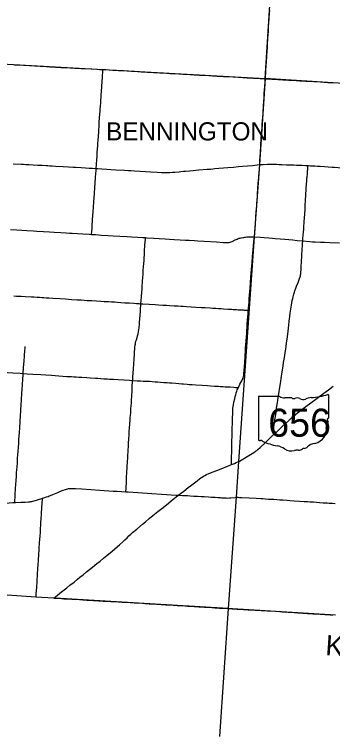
# Model space of a CAD drawing. Extents: x 1815539 to 1947826, y 273303 to 993194.
# Drawn here: x 1889640 to 1905397, y 849557 to 885394 of the extents above; entities that cross this region are included whole.
import ezdxf

# ---------------------------------------------------------------- set-up
doc = ezdxf.new("R2010")
doc.units = 0
for name, color, linetype in [('GM_X_Adjacent_County_Text', 7, 'Continuous'), ('GM_X_County', 7, 'Continuous'), ('GM_X_County_Road', 7, 'Continuous'), ('GM_X_State_Route', 7, 'Continuous'), ('GM_X_Township', 7, 'Continuous'), ('GM_X_Township_Road', 7, 'Continuous'), ('GM_X_Township_Text', 7, 'Continuous'), ('PV_X_EOP', 7, 'Continuous'), ('SC_Shading3', 7, 'Continuous')]:
    doc.layers.add(name, color=color, linetype=linetype)

msp = doc.modelspace()

# ---------------------------------------------------------------- linework, layer by layer
at = {"layer": 'GM_X_County'}
msp.add_lwpolyline([(1905546, 855583), (1900992, 855867), (1900447, 855895), (1900228, 855908), (1896895, 856116), (1891937, 856405), (1891588, 856432), (1890695, 856480), (1886895, 856734)], dxfattribs=at)
at = {"layer": 'GM_X_County_Road'}
for points in [[(1902064, 882205), (1902069, 882271), (1902089, 882549), (1902097, 882680), (1902104, 882794), (1902124, 883088), (1902135, 883252), (1902142, 883350), (1902160, 883579), (1902171, 883759), (1902179, 883906), (1902198, 884217), (1902218, 884561), (1902232, 884790), (1902259, 885182), (1902277, 885477), (1902284, 885593)], [(1901788, 877939), (1901801, 878159), (1901811, 878322), (1901825, 878552), (1901847, 878896), (1901869, 879256), (1901894, 879616), (1901903, 879780), (1901914, 879927), (1901928, 880124), (1901938, 880255), (1901953, 880500), (1901979, 880877), (1901991, 881073), (1902003, 881270), (1902016, 881499), (1902024, 881630), (1902038, 881827), (1902052, 882023), (1902064, 882205)], [(1902064, 882205), (1902240, 882194), (1902387, 882186), (1902682, 882168), (1902927, 882155), (1903239, 882138), (1903403, 882129), (1903779, 882107), (1903910, 882101), (1904074, 882090), (1904222, 882082), (1904467, 882068), (1904598, 882059), (1904795, 882046), (1904975, 882034), (1905171, 882022), (1905449, 882003)], [(1901526, 874352), (1901541, 874540), (1901560, 874771), (1901575, 874967), (1901585, 875124), (1901590, 875197), (1901597, 875311), (1901620, 875605), (1901640, 875884), (1901650, 876015), (1901672, 876326), (1901686, 876522), (1901701, 876718), (1901721, 876997), (1901743, 877291), (1901752, 877406), (1901760, 877537), (1901773, 877733), (1901788, 877939)], [(1891033, 861391), (1891103, 861412), (1891228, 861451), (1891306, 861477), (1891367, 861499), (1891427, 861524), (1891533, 861569), (1891790, 861677), (1891927, 861733), (1892050, 861779), (1892174, 861823), (1892221, 861838), (1892284, 861856), (1892317, 861863), (1892340, 861867), (1892376, 861873), (1892414, 861874), (1892457, 861874), (1892511, 861873), (1892657, 861863), (1892975, 861844), (1893875, 861784), (1894530, 861742), (1894727, 861729), (1895156, 861701)], [(1895156, 861701), (1895267, 861694), (1895758, 861664), (1896445, 861620), (1896920, 861591), (1897657, 861542), (1897691, 861539), (1897763, 861534)], [(1897763, 861534), (1897839, 861530), (1897960, 861524), (1898208, 861515), (1898338, 861507), (1898526, 861493), (1898704, 861483), (1898895, 861472), (1899045, 861464), (1899246, 861452), (1899400, 861441), (1899581, 861430), (1899712, 861422), (1899842, 861413), (1899917, 861408)], [(1887166, 860572), (1887216, 860614), (1887308, 860683), (1887494, 860818), (1887640, 860924), (1887720, 860982), (1887748, 861000), (1887777, 861016), (1887808, 861028), (1887824, 861033), (1887840, 861037), (1887873, 861041), (1888069, 861059), (1888315, 861078), (1888511, 861093), (1888609, 861101), (1889018, 861133), (1889182, 861145), (1889378, 861158), (1889558, 861167), (1889657, 861171)], [(1889657, 861171), (1889692, 861173), (1889953, 861185), (1890166, 861196), (1890328, 861205), (1890402, 861211), (1890451, 861216), (1890507, 861229), (1890555, 861240), (1890618, 861258), (1890993, 861378), (1891033, 861391)], [(1899917, 861408), (1899957, 861406), (1900023, 861403), (1900085, 861399)], [(1900085, 861399), (1900121, 861397), (1900203, 861395), (1900285, 861397), (1900367, 861402), (1900580, 861425), (1900581, 861425)], [(1900581, 861425), (1900655, 861430), (1900723, 861431), (1900792, 861429), (1900906, 861425), (1901275, 861404), (1901620, 861382), (1901838, 861371), (1901949, 861365), (1902082, 861356), (1902229, 861346), (1902336, 861340), (1902491, 861330), (1902642, 861318), (1902782, 861311), (1902943, 861304), (1903156, 861289), (1903274, 861276), (1903498, 861259), (1903761, 861241), (1903998, 861229), (1904157, 861221), (1904294, 861213), (1904450, 861200), (1904752, 861174), (1904940, 861161), (1905132, 861150), (1905237, 861146), (1905393, 861139), (1905528, 861131)], [(1891583, 856425), (1891639, 856423), (1891746, 856417), (1891965, 856405)], [(1891965, 856405), (1892090, 856398), (1892301, 856385), (1892481, 856374), (1892856, 856351), (1893019, 856342), (1893232, 856329), (1893543, 856312), (1893805, 856297), (1893879, 856293), (1894034, 856284), (1894263, 856272), (1894410, 856264), (1894495, 856259)], [(1894495, 856259), (1894590, 856253), (1894770, 856241), (1894983, 856228), (1895376, 856205), (1895572, 856194), (1895703, 856186), (1895981, 856169), (1896095, 856161), (1896177, 856156), (1896242, 856153), (1896308, 856149), (1896553, 856136), (1896684, 856128), (1896799, 856122), (1896913, 856115), (1896923, 856115)], [(1896923, 856115), (1897028, 856108), (1897142, 856101), (1897208, 856097), (1897503, 856079), (1897601, 856072), (1897699, 856066), (1897780, 856061), (1897911, 856054), (1898222, 856035), (1898370, 856027), (1898550, 856015), (1898713, 856004), (1898778, 856000), (1898893, 855993), (1899057, 855983), (1899416, 855960), (1899563, 855950), (1899678, 855942), (1899792, 855935), (1899988, 855922), (1900186, 855910)], [(1900186, 855910), (1900418, 855898), (1900516, 855892), (1900679, 855880), (1900711, 855878), (1900792, 855875), (1900873, 855872), (1900987, 855865), (1901117, 855858), (1901216, 855852), (1901412, 855841), (1901477, 855838), (1901559, 855834), (1901730, 855823), (1901855, 855815), (1902001, 855805), (1902166, 855796), (1902566, 855776), (1902784, 855762), (1902899, 855755), (1903029, 855748), (1903195, 855737), (1903359, 855726), (1903490, 855716), (1903572, 855710), (1903686, 855702), (1903866, 855689), (1903948, 855683), (1904151, 855671), (1904291, 855661), (1904422, 855654), (1904635, 855643), (1904787, 855633), (1904900, 855626), (1905019, 855619), (1905109, 855614), (1905174, 855610), (1905275, 855603), (1905405, 855595)]]:
    msp.add_lwpolyline(points, dxfattribs=at)
at = {"layer": 'GM_X_State_Route'}
for points in [[(1889446, 874722), (1889758, 874704), (1890249, 874670), (1890576, 874650), (1890756, 874639), (1891084, 874620), (1891379, 874602), (1891608, 874588), (1891936, 874570), (1892198, 874556), (1892362, 874545), (1892493, 874537), (1892771, 874520), (1893033, 874504), (1893344, 874485), (1893457, 874478), (1893655, 874466), (1893950, 874446), (1894278, 874425), (1894523, 874409), (1894867, 874390), (1895227, 874371), (1895440, 874359), (1895735, 874340), (1895999, 874324), (1896130, 874316), (1896194, 874311), (1896545, 874289), (1896816, 874273), (1897111, 874256), (1897318, 874243), (1897553, 874228), (1897848, 874210), (1898110, 874195), (1898295, 874184), (1898552, 874168), (1898716, 874157), (1899043, 874137), (1899649, 874101), (1899993, 874075), (1900091, 874069), (1900157, 874068), (1900207, 874070), (1900240, 874073), (1900272, 874079), (1900320, 874091), (1900367, 874108), (1900428, 874133), (1900576, 874203), (1900666, 874244), (1900727, 874268), (1900773, 874283), (1900820, 874296), (1900868, 874306), (1900948, 874320), (1901007, 874330), (1901046, 874336), (1901092, 874342), (1901155, 874349), (1901230, 874356), (1901307, 874358), (1901372, 874358), (1901479, 874355), (1901526, 874352), (1901827, 874333), (1902007, 874320), (1902236, 874305), (1902416, 874291), (1902563, 874278), (1902808, 874257), (1903037, 874237), (1903429, 874202), (1903641, 874181), (1903918, 874156), (1903926, 874155), (1904277, 874122), (1904408, 874113), (1904539, 874106), (1904801, 874094), (1904997, 874087), (1905259, 874074), (1905735, 874054)], [(1891583, 856425), (1891666, 856492), (1891977, 856734), (1892233, 856938), (1892386, 857062), (1892590, 857227), (1892769, 857371), (1892883, 857465), (1893036, 857588), (1893214, 857733), (1893354, 857847), (1893507, 857970), (1893725, 858144), (1893878, 858268), (1894056, 858412), (1894208, 858537), (1894474, 858756), (1894751, 858988), (1894850, 859074), (1895018, 859229), (1895114, 859320), (1895219, 859423), (1895313, 859515), (1895397, 859593), (1895495, 859680), (1895694, 859850), (1895983, 860092), (1896133, 860220), (1896321, 860378), (1896502, 860529), (1896742, 860718), (1896934, 860871), (1897088, 860994), (1897266, 861138), (1897408, 861250), (1897574, 861383), (1897740, 861517), (1897763, 861534), (1897869, 861618), (1898025, 861739), (1898243, 861912), (1898360, 862002), (1898683, 862253), (1898814, 862353), (1898880, 862401), (1898934, 862437), (1899004, 862479), (1899076, 862519), (1899149, 862555), (1899239, 862595), (1899436, 862676), (1899665, 862767), (1899878, 862851), (1900198, 862977), (1900351, 863038), (1900389, 863053), (1900536, 863112), (1900631, 863153), (1900707, 863188), (1900715, 863192), (1900793, 863231), (1900864, 863272), (1900956, 863324), (1901044, 863377), (1901174, 863454), (1901326, 863549), (1901497, 863655), (1901582, 863713), (1901644, 863757), (1901696, 863800), (1901806, 863898), (1902080, 864158), (1902377, 864442), (1902555, 864611), (1902581, 864636), (1902759, 864802), (1902926, 864957), (1903205, 865215), (1903322, 865323), (1903470, 865459), (1903569, 865546), (1903638, 865602), (1903736, 865683), (1903878, 865788), (1904009, 865886), (1904326, 866120), (1904577, 866305), (1904761, 866443), (1904971, 866600), (1905195, 866767), (1905433, 866942)]]:
    msp.add_lwpolyline(points, dxfattribs=at)
at = {"layer": 'GM_X_Township'}
for points in [[(1929313, 880637), (1926519, 880798), (1923978, 880945), (1923826, 880954), (1918127, 881283), (1915079, 881414), (1912418, 881561), (1907482, 881867), (1902065, 882212), (1902276, 885593), (1902366, 887154), (1902378, 887248), (1902624, 890798), (1902935, 895772), (1903241, 901246), (1903453, 905734), (1903500, 906547), (1903661, 909327)], [(1888679, 882953), (1894036, 882664), (1902065, 882212), (1901776, 877944), (1901523, 874357), (1900741, 863210), (1900616, 861438), (1900228, 855908)]]:
    msp.add_lwpolyline(points, dxfattribs=at)
at = {"layer": 'GM_X_Township_Road'}
for points in [[(1889638, 882899), (1889900, 882886), (1890081, 882876), (1890195, 882871), (1890384, 882860), (1890638, 882845), (1890769, 882838), (1890917, 882829), (1891064, 882822), (1891228, 882813), (1891394, 882800), (1891544, 882791), (1891669, 882783), (1891850, 882772), (1891941, 882767), (1892085, 882760), (1892195, 882754), (1892392, 882744), (1892636, 882731), (1892833, 882720), (1892951, 882714), (1893097, 882707), (1893474, 882689), (1893720, 882676), (1893852, 882669), (1893926, 882665), (1894024, 882660)], [(1893689, 877747), (1893702, 877943), (1893722, 878205), (1893730, 878335), (1893745, 878564), (1893768, 878875), (1893777, 879006), (1893785, 879136), (1893800, 879349), (1893816, 879561), (1893825, 879692), (1893831, 879807), (1893836, 879905), (1893838, 879959), (1893842, 880064), (1893853, 880245), (1893871, 880456), (1893880, 880575), (1893889, 880700), (1893900, 880836), (1893912, 880999), (1893938, 881408), (1893948, 881572), (1893966, 881817), (1893984, 882062), (1893997, 882275), (1894003, 882373), (1894013, 882520), (1894024, 882660)], [(1894024, 882660), (1894170, 882653), (1894350, 882644), (1894514, 882635), (1894694, 882625), (1894792, 882618), (1894939, 882610), (1895037, 882604), (1895283, 882591), (1895446, 882582), (1895593, 882572), (1895747, 882563), (1895827, 882558), (1895924, 882553), (1896045, 882546), (1896215, 882536), (1896297, 882532), (1896395, 882527), (1896526, 882519), (1896673, 882510), (1896836, 882499), (1896951, 882491), (1897016, 882488), (1897196, 882479), (1897360, 882470), (1897572, 882457), (1897785, 882444), (1897883, 882439), (1897981, 882434), (1898079, 882428), (1898341, 882412), (1898537, 882400), (1898619, 882395), (1898799, 882384), (1899011, 882373), (1899273, 882359), (1899453, 882350), (1899551, 882345), (1899682, 882338), (1899846, 882329), (1900000, 882320), (1900238, 882308), (1900468, 882297), (1900746, 882279), (1901171, 882253), (1901384, 882243), (1901482, 882239), (1901645, 882228), (1901809, 882218), (1902064, 882205)], [(1889574, 877988), (1889972, 877965), (1890083, 877958), (1890202, 877951), (1890348, 877942), (1890573, 877932), (1890802, 877920), (1891015, 877908), (1891211, 877896), (1891300, 877891), (1891394, 877886), (1891514, 877878), (1891670, 877870), (1892046, 877846), (1892325, 877828), (1892554, 877814), (1892669, 877807), (1892947, 877790), (1893160, 877777), (1893340, 877766), (1893504, 877758), (1893689, 877747)], [(1893457, 874478), (1893459, 874511), (1893467, 874609), (1893482, 874821), (1893497, 875001), (1893502, 875083), (1893511, 875213), (1893524, 875393), (1893539, 875606), (1893554, 875818), (1893573, 876113), (1893586, 876292), (1893599, 876505), (1893619, 876799), (1893636, 877028), (1893655, 877306), (1893672, 877502), (1893681, 877633), (1893689, 877747)], [(1893689, 877747), (1893764, 877742), (1893962, 877731), (1894224, 877713), (1894421, 877700), (1894666, 877685), (1895092, 877658), (1895289, 877648), (1895410, 877641), (1895583, 877632), (1895862, 877617), (1896124, 877602), (1896403, 877585), (1896714, 877565), (1896927, 877552), (1897058, 877544), (1897156, 877542), (1897205, 877542), (1897336, 877551), (1897467, 877561), (1897581, 877569), (1897794, 877588), (1897875, 877596), (1898022, 877609), (1898120, 877618), (1898316, 877636), (1898496, 877653), (1898627, 877664), (1898774, 877675), (1899183, 877708), (1899347, 877721), (1899461, 877731), (1899559, 877740), (1899772, 877758), (1900000, 877777), (1900213, 877795), (1900491, 877819), (1900736, 877841), (1900932, 877858), (1901177, 877881), (1901439, 877905), (1901668, 877926), (1901788, 877939)], [(1901788, 877939), (1901890, 877947), (1901955, 877950), (1902168, 877955), (1902349, 877960), (1902464, 877960), (1902628, 877957), (1902759, 877952), (1902890, 877946), (1903119, 877938), (1903267, 877932), (1903381, 877928), (1903480, 877924), (1903611, 877918), (1903873, 877907), (1904053, 877899), (1904181, 877893)], [(1904132, 877278), (1904134, 877308), (1904153, 877504), (1904160, 877603), (1904169, 877717), (1904176, 877799), (1904179, 877848), (1904181, 877893)], [(1904181, 877893), (1904201, 877892), (1904299, 877888), (1904430, 877881), (1904512, 877877), (1904659, 877867), (1904790, 877859), (1905003, 877844), (1905183, 877832), (1905379, 877820), (1905494, 877813), (1905854, 877787), (1906214, 877763), (1906574, 877738), (1906721, 877728), (1906918, 877717), (1906935, 877716)], [(1903926, 874155), (1903934, 874260), (1903947, 874457), (1903957, 874588), (1903969, 874735), (1903982, 874899), (1903993, 875030), (1903998, 875095), (1904015, 875308), (1904026, 875488), (1904038, 875734), (1904046, 875898), (1904062, 876193), (1904072, 876407), (1904077, 876489), (1904089, 876669), (1904096, 876784), (1904106, 876931), (1904121, 877145), (1904132, 877278)], [(1895904, 871035), (1895904, 871044), (1895914, 871175), (1895931, 871420), (1895959, 871780), (1895972, 871960), (1895978, 872059), (1895987, 872190), (1895995, 872304), (1896011, 872534), (1896021, 872681), (1896034, 872878), (1896045, 873018), (1896058, 873201), (1896066, 873320), (1896076, 873467), (1896081, 873549), (1896087, 873647), (1896106, 873942), (1896114, 874085), (1896125, 874242), (1896130, 874316)], [(1901228, 870711), (1901236, 870824), (1901247, 870972), (1901259, 871136), (1901273, 871316), (1901282, 871430), (1901289, 871511), (1901297, 871609), (1901315, 871822), (1901335, 872084), (1901356, 872345), (1901372, 872558), (1901387, 872738), (1901415, 873081), (1901440, 873359), (1901454, 873539), (1901467, 873719), (1901485, 873915), (1901505, 874128), (1901517, 874258), (1901526, 874352)], [(1902581, 864636), (1902566, 864657), (1902529, 864711), (1902511, 864739), (1902504, 864753), (1902498, 864769), (1902494, 864784), (1902491, 864801), (1902489, 864817), (1902489, 864850), (1902493, 864899), (1902510, 865029), (1902525, 865143), (1902543, 865272), (1902554, 865354), (1902566, 865435), (1902584, 865548), (1902602, 865661), (1902629, 865839), (1902645, 865953), (1902671, 866132), (1902686, 866229), (1902710, 866391), (1902738, 866569), (1902755, 866682), (1902768, 866780), (1902785, 866893), (1902816, 867071), (1902839, 867200), (1902859, 867330), (1902876, 867443), (1902889, 867541), (1902903, 867638), (1902920, 867752), (1902948, 867946), (1902973, 868125), (1902998, 868287), (1903027, 868465), (1903048, 868611), (1903061, 868692), (1903076, 868789), (1903095, 868919), (1903122, 869097), (1903147, 869276), (1903179, 869519), (1903200, 869682), (1903217, 869829), (1903235, 869992), (1903253, 870154), (1903270, 870301), (1903279, 870366), (1903285, 870414), (1903305, 870577), (1903318, 870674), (1903346, 870869), (1903361, 870966), (1903382, 871079), (1903403, 871191), (1903423, 871304), (1903440, 871384), (1903457, 871448), (1903477, 871510), (1903508, 871603), (1903535, 871681), (1903579, 871804), (1903620, 871911), (1903688, 872096), (1903762, 872296), (1903788, 872374), (1903802, 872421), (1903812, 872469), (1903819, 872518), (1903825, 872583), (1903836, 872730), (1903845, 872894), (1903859, 873107), (1903879, 873434), (1903897, 873729), (1903909, 873925), (1903916, 874023), (1903925, 874145), (1903926, 874155)], [(1889602, 871431), (1889749, 871420), (1889913, 871409), (1889979, 871405), (1890175, 871396), (1890487, 871382), (1890601, 871375), (1890757, 871365), (1890873, 871356), (1890990, 871349), (1891091, 871343), (1891207, 871337), (1891336, 871329), (1891534, 871317), (1891911, 871290), (1892173, 871273), (1892467, 871254), (1892746, 871236), (1892942, 871224), (1893237, 871205), (1893468, 871191), (1893712, 871176), (1893925, 871165), (1894089, 871155), (1894302, 871142), (1894449, 871133), (1894596, 871123), (1894727, 871114), (1894917, 871101), (1895106, 871089), (1895235, 871081), (1895317, 871076), (1895547, 871061), (1895693, 871050), (1895807, 871042), (1895857, 871039), (1895895, 871036), (1895904, 871035)], [(1895496, 867229), (1895507, 867386), (1895534, 867804), (1895549, 868044), (1895567, 868303), (1895581, 868515), (1895591, 868679), (1895597, 868761), (1895609, 868892), (1895619, 868973), (1895629, 869038), (1895641, 869102), (1895660, 869181), (1895678, 869244), (1895718, 869369), (1895740, 869448), (1895764, 869543), (1895785, 869640), (1895806, 869752), (1895815, 869817), (1895824, 869898), (1895830, 869996), (1895839, 870127), (1895851, 870274), (1895867, 870482), (1895878, 870634), (1895891, 870814), (1895898, 870929), (1895904, 871035)], [(1895904, 871035), (1896000, 871029), (1896311, 871010), (1896605, 870991), (1896769, 870982), (1896998, 870970), (1897179, 870960), (1897326, 870950), (1897545, 870938), (1897726, 870926), (1897886, 870916), (1897997, 870910), (1898161, 870900), (1898619, 870873), (1898898, 870854), (1899094, 870842), (1899340, 870827), (1899471, 870819), (1899618, 870810), (1899749, 870802), (1899781, 870799), (1899879, 870794), (1899994, 870787), (1900223, 870774), (1900305, 870768), (1900387, 870763), (1900469, 870758), (1900632, 870746), (1900725, 870741), (1900838, 870734), (1900913, 870730), (1900966, 870727), (1901018, 870725), (1901092, 870719), (1901214, 870712), (1901228, 870711)], [(1901071, 868478), (1901073, 868517), (1901081, 868648), (1901093, 868828), (1901116, 869172), (1901131, 869401), (1901144, 869565), (1901154, 869712), (1901164, 869876), (1901175, 870040), (1901188, 870236), (1901202, 870400), (1901213, 870531), (1901225, 870678), (1901228, 870711)], [(1890073, 867578), (1890091, 867851), (1890117, 868211), (1890133, 868440), (1890143, 868555), (1890151, 868635), (1890159, 868715), (1890167, 868815), (1890174, 868910)], [(1900721, 866865), (1900749, 866921), (1900810, 867037), (1900900, 867212), (1900959, 867329), (1900978, 867375), (1900988, 867406), (1900999, 867454), (1901007, 867502), (1901011, 867551), (1901022, 867732), (1901034, 867912), (1901050, 868141), (1901068, 868419), (1901071, 868478)], [(1887670, 867741), (1887682, 867740), (1887720, 867737), (1887766, 867733), (1887972, 867716), (1888088, 867706), (1888176, 867698), (1888264, 867693), (1888364, 867688), (1888507, 867679), (1888673, 867670), (1888883, 867658), (1889113, 867643), (1889291, 867630), (1889560, 867612), (1889920, 867588), (1890068, 867578), (1890073, 867578)], [(1889657, 861171), (1889658, 861209), (1889660, 861291), (1889668, 861415), (1889676, 861537), (1889682, 861643), (1889693, 861798), (1889697, 861864), (1889707, 862060), (1889720, 862257), (1889736, 862486), (1889749, 862666), (1889769, 862928), (1889784, 863158), (1889797, 863338), (1889814, 863567), (1889821, 863682), (1889835, 863911), (1889849, 864108), (1889863, 864321), (1889885, 864632), (1889901, 864894), (1889919, 865156), (1889941, 865500), (1889952, 865681), (1889961, 865828), (1889972, 865975), (1889992, 866320), (1890007, 866549), (1890026, 866828), (1890035, 866959), (1890060, 867352), (1890065, 867448), (1890073, 867567), (1890073, 867578)], [(1890073, 867578), (1890264, 867565), (1890542, 867546), (1890952, 867519), (1891186, 867504), (1891475, 867484), (1891832, 867461), (1892228, 867433), (1892458, 867420), (1892589, 867412), (1892703, 867406), (1892834, 867399), (1892982, 867389), (1893223, 867373), (1893391, 867361), (1893653, 867344), (1893767, 867337), (1894062, 867318), (1894242, 867307), (1894341, 867301), (1894421, 867295), (1894550, 867288), (1894779, 867274), (1895057, 867256), (1895336, 867238), (1895496, 867229)], [(1895156, 861701), (1895158, 861724), (1895168, 861855), (1895185, 862232), (1895189, 862351), (1895195, 862496), (1895202, 862591), (1895209, 862710), (1895218, 862885), (1895227, 863003), (1895235, 863130), (1895243, 863246), (1895249, 863343), (1895256, 863425), (1895262, 863539), (1895270, 863678), (1895278, 863788), (1895287, 863954), (1895297, 864164), (1895304, 864283), (1895311, 864397), (1895316, 864469), (1895318, 864537), (1895322, 864628), (1895325, 864684), (1895329, 864750), (1895335, 864851), (1895354, 865098), (1895364, 865238), (1895377, 865377), (1895389, 865514), (1895398, 865612), (1895413, 865841), (1895430, 866102), (1895437, 866258), (1895448, 866453), (1895465, 866708), (1895472, 866850), (1895479, 866996), (1895486, 867110), (1895494, 867214), (1895496, 867229)], [(1895496, 867229), (1895720, 867217), (1895883, 867207), (1896013, 867200), (1896154, 867193), (1896234, 867191), (1896351, 867186), (1896468, 867179), (1896614, 867169), (1896746, 867158), (1896878, 867147), (1897038, 867134), (1897201, 867121), (1897316, 867112), (1897430, 867104), (1897630, 867088), (1897779, 867075), (1897928, 867063), (1898017, 867055), (1898199, 867040), (1898319, 867032), (1898445, 867024), (1898632, 867011), (1898940, 866993), (1899197, 866975), (1899345, 866966), (1899557, 866952), (1899754, 866940), (1899836, 866935), (1899983, 866926), (1900081, 866921), (1900327, 866907), (1900507, 866895), (1900589, 866888), (1900637, 866882), (1900686, 866872), (1900721, 866865)], [(1900389, 863053), (1900390, 863142), (1900391, 863289), (1900396, 863453), (1900401, 863650), (1900406, 863847), (1900414, 864224), (1900421, 864486), (1900425, 864667), (1900425, 864749), (1900428, 864864), (1900435, 865091), (1900440, 865290), (1900453, 865667), (1900458, 865782), (1900464, 865847), (1900477, 865945), (1900490, 866026), (1900514, 866155), (1900549, 866315), (1900575, 866427), (1900601, 866522), (1900629, 866618), (1900655, 866698), (1900678, 866761), (1900699, 866812), (1900720, 866862), (1900721, 866865)], [(1890717, 856500), (1890716, 856519), (1890717, 856546), (1890718, 856566), (1890722, 856632), (1890734, 856796), (1890747, 856976), (1890766, 857238), (1890789, 857631), (1890802, 857860), (1890819, 858106), (1890829, 858270), (1890835, 858384), (1890845, 858531), (1890854, 858662), (1890860, 858760), (1890870, 858907), (1890886, 859169), (1890897, 859348), (1890909, 859495), (1890922, 859708), (1890936, 859920), (1890941, 860018), (1890952, 860182), (1890964, 860362), (1890977, 860591), (1891001, 860935), (1891012, 861116), (1891029, 861345), (1891032, 861382), (1891033, 861391)]]:
    msp.add_lwpolyline(points, dxfattribs=at)
at = {"layer": 'PV_X_EOP'}
msp.add_line((1900228, 855908), (1899800, 849557), dxfattribs=at)
at = {"layer": 'SC_Shading3'}
for p, q in [((1901727, 866402), (1901727, 864288)), ((1902780, 866438), (1901761, 866438)), ((1905207, 865385), (1905207, 866490)), ((1905207, 865385), (1905207, 865385))]:
    msp.add_line(p, q, dxfattribs=at)
for centre, major_axis, start_param, end_param in [((1901767, 866406), (40.3, 0), 1.712693, 3.28349), ((1903023, 866683), (391, 0), 4.042523, 4.731795), ((1903153, 865252), (1404, 0), 1.404758, 1.657858), ((1903471, 866417), (113, 0), 3.836095, 5.185415), ((1903637, 866173), (235, 0), 0.950623, 2.079405), ((1903940, 866508), (282, 0), 4.081561, 5.145723), ((1904438, 865793), (743, 0), 1.699011, 2.107814), ((1903967, 869319), (3691, 0), 4.814394, 5.042369), ((1905168, 866495), (38.7, 0), 6.141152, 7.989035), ((1905198, 865304), (60, 0), 1.883978, 3.671073), ((1904817, 865164), (360, 0), 5.934695, 6.695948), ((1905166, 865381), (41.5, 0), 5.05454, 6.418171), ((1904174, 864782), (923, 0), 5.101752, 6.440018), ((1905346, 864922), (262, 0), 2.387724, 3.262537), ((1901767, 864284), (40.7, 0), 3.00124, 4.508301), ((1901773, 864500), (310, 0), 4.665946, 4.897461), ((1901837, 864167), (112, 0), 0.519207, 1.627899), ((1903250, 866065), (2665, 0), 4.195997, 4.488961), ((1904563, 863695), (506, 0), 1.647645, 2.488434), ((1902455, 863339), (834, 0), 0.823519, 1.323587), ((1903357, 864156), (529, 0), 4.026481, 4.996735), ((1903663, 863425), (435, 0), 1.495662, 1.94098), ((1903702, 863998), (282, 0), 4.691044, 5.507374), ((1903957, 863793), (79.4, 0), 1.147584, 2.315152), ((1903923, 864084), (298, 0), 4.937069, 5.64225)]:
    msp.add_ellipse(centre, major_axis=major_axis, ratio=0.8, start_param=start_param, end_param=end_param, dxfattribs=at)

# ---------------------------------------------------------------- texts
at = {"layer": 'GM_X_Adjacent_County_Text'}
msp.add_text('KNOX COUNTY', height=1000, rotation=356.2231, dxfattribs=at).set_placement((1905024, 853603))
at = {"layer": 'GM_X_Township_Text'}
msp.add_text('BENNINGTON', height=900, rotation=0, dxfattribs=at).set_placement((1894178, 879141))
at = {"layer": 'SC_Shading3'}
msp.add_text('656', height=1392.2, dxfattribs=at).set_placement((1902212, 864437))

doc.saveas('drawing.dxf')
